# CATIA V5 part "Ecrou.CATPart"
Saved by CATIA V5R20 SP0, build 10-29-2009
Part number: Ecrou
Bounding box of the stored display mesh (mm): x -29.774 to -18.226, y 45.5 to 50.5, z -16 to -6
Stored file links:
  E:\Boulot\SeaTech\2eme ANNEE\FabricationAdditive\TP_MOSM_CREM\Projet Sauterelle de serrage\CAO Assemblage Sauterelle\Ecrou.CATPart
  E:\Boulot\SeaTech\2eme ANNEE\FabricationAdditive\TP_MOSM_CREM\Projet Sauterelle de serrage\CAO Assemblage Sauterelle\Sauterelle_horizontale_05120-06.CATPart
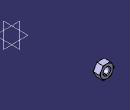
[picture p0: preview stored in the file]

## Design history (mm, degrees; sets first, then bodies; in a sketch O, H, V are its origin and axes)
Body1 (main body)
  Solid1 "05120-06_8": solid without history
